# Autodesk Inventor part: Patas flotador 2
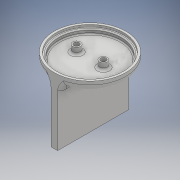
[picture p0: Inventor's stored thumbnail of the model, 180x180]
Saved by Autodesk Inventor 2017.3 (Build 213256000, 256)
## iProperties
Part Number: Patas flotador 2
Material: Genérico
Document SubType Name: Modeling
Designer: PABLO HERNANDEZ
Density: 1 g/cm^3
Appearance: Valor por defecto
Author: PABLO HERNANDEZ
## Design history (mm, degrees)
sketch "Boceto1"
  geometry: C1 r 16 at (0, 0); 1 further point
  constraints: 1 centre point, 1 coincident
  dimensions: "d0" = 32 diameter of C1
extrude "Extrusión1" new body sketch "Boceto1" distance "d1" = 1; taper "d2" = 0 deg; dims "d93" = 1, "d94" = 0
sketch "Boceto2"
  geometry: C1 r 16 at (0, 0); C2 r 15 at (0, 0); C3 r 14 at (0, 0); 1 further point
  constraints: 3 centre point, 1 coincident
  dimensions: "d3" = 1 radial gap between concentric circles of C1 C2; "d4" = 1 radial gap between concentric circles of C2 C3
extrude "Extrusión2" join sketch "Boceto2" distance "d5" = 3; taper "d6" = 0 deg
sketch "Boceto3"
  geometry: C1 r 15 at (0, 0); C2 r 14 at (0, 0); 1 further point
  constraints: 2 centre point, 1 coincident
  dimensions: "d7" = 1 radial gap between concentric circles of C1 C2; "d123" = 30 diameter of C1
extrude "Extrusión3" join sketch "Boceto3" distance "d8" = 2; taper "d9" = 0 deg
sketch "Boceto4"
  geometry: C1 r 16 at (0, 0); 1 further point
  constraints: 1 centre point, 1 coincident
extrude "Extrusión4" cut sketch "Boceto4" distance "d10" = 0.5; taper "d11" = 0 deg
sketch "Boceto7"
  geometry: L1 (1.5, -15.93)-(1.5, 15.93); L2 (-1.5, -15.93)-(-1.5, 15.93); A1 r 16 centre (0, 0) between (1.5, 15.93) and (-1.5, 15.93); A2 r 16 centre (0, 0) between (-1.5, -15.93) and (1.5, -15.93); 2 further points
  constraints: 4 end point, 4 point on circle, 2 centre point, 1 coincident
extrude "Extrusión7" join sketch "Boceto7" distance "d63" = 25; taper "d64" = 0 deg
fillet "Empalme1" dims "d71" = 2
fillet "Empalme2" dims "d95" = 3
fillet "Empalme3" dims "d96" = 0.5
sketch "Boceto12"
  geometry: C1 r 1.2 at (-6, 0); C2 r 1.2 at (6, 0); 2 further points
  constraints: 2 centre point, 1 coincident
  dimensions: "d104" = 6 distance of point (0, 0) point (-6, 0); "d114" = 2.4 diameter of C1; "d115" = 2.4 diameter of C2
extrude "Extrusión9" cut sketch "Boceto12" stored distance "d116" = 10; taper "d117" = 0 deg
sketch "Boceto13"
  geometry: C1 r 1.2 at (-6, 0) reference; C2 r 1.75 at (-6, 0); C3 r 1.2 at (6, 0) reference; C4 r 1.75 at (6, 0); 1 further point
  constraints: 2 centre point, 2 coincident
  dimensions: "d118" = 3.5 diameter of C2; "d119" = 3.5 diameter of C4
extrude "Extrusión10" join sketch "Boceto13" distance "d120" = 3; taper "d121" = 0 deg
fillet "Empalme4" dims "d122" = 1
sketch "Boceto14"
  geometry: 1 further point
sketch "Boceto15"
  geometry: C1 r 1.2 at (6, 0) reference; C2 r 2.5 at (6, 0); C3 r 1.2 at (-6, 0) reference; C4 r 2.5 at (-6, 0); 1 further point
  constraints: 2 centre point, 2 coincident
  dimensions: "d124" = 5 diameter of C2; "d125" = 5 diameter of C4
extrude "Extrusión11" cut sketch "Boceto15" distance "d126" = 10; taper "d127" = 0 deg
node "Sólido1"
other parameters: "sa_0" = 4
